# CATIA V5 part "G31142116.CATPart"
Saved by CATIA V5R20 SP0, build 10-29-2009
Part number: G31209022
Revision: 11
Definition: design
Nomenclature: G31209022
Source: made
Description: NOT SPECIFIED
Bounding box of the stored display mesh (mm): x -5 to 22, y -8 to 8, z -8 to 8
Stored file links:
  C:\Users\Raffaele\Desktop\3D X SITO CF\BOLEX\23-BUSH REF 312\G31142116.CATPart

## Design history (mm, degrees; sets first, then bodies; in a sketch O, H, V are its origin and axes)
Body1 "MANIFOLD_SOLID_BREP #5459" (main body)
  Solid1: solid without history
Body2 "MANIFOLD_SOLID_BREP #5602"
  Solid2: solid without history
Body3 "MANIFOLD_SOLID_BREP #5745"
  Solid3: solid without history
Body4 "MANIFOLD_SOLID_BREP #5888"
  Solid4: solid without history
Body5 "MANIFOLD_SOLID_BREP #6031"
  Solid5: solid without history
Body6 "MANIFOLD_SOLID_BREP #6174"
  Solid6: solid without history
Body7 "MANIFOLD_SOLID_BREP #6317"
  Solid7: solid without history
Body8 "MANIFOLD_SOLID_BREP #6462"
  Solid8: solid without history
Body9 "MANIFOLD_SOLID_BREP #6607"
  Solid9: solid without history
Body10 "MANIFOLD_SOLID_BREP #6752"
  Solid10: solid without history
Body11 "MANIFOLD_SOLID_BREP #6897"
  Solid11: solid without history
Body12 "MANIFOLD_SOLID_BREP #7040"
  Solid12: solid without history
Body13 "MANIFOLD_SOLID_BREP #7183"
  Solid13: solid without history
Body14 "MANIFOLD_SOLID_BREP #7328"
  Solid14: solid without history
Body15 "MANIFOLD_SOLID_BREP #7473"
  Solid15: solid without history
Body16 "MANIFOLD_SOLID_BREP #7618"
  Solid16: solid without history
Body17 "MANIFOLD_SOLID_BREP #7763"
  Solid17: solid without history
Body18 "MANIFOLD_SOLID_BREP #7908"
  Solid18: solid without history
Body19 "MANIFOLD_SOLID_BREP #8053"
  Solid19: solid without history
Body20 "MANIFOLD_SOLID_BREP #8196"
  Solid20: solid without history
Body21 "MANIFOLD_SOLID_BREP #8339"
  Solid21: solid without history
Body22 "MANIFOLD_SOLID_BREP #8484"
  Solid22: solid without history
Body23 "MANIFOLD_SOLID_BREP #8629"
  Solid23: solid without history
Body24 "MANIFOLD_SOLID_BREP #8774"
  Solid24: solid without history
Body25 "MANIFOLD_SOLID_BREP #8919"
  Solid25: solid without history
Body26 "MANIFOLD_SOLID_BREP #9064"
  Solid26: solid without history
Body27 "MANIFOLD_SOLID_BREP #9207"
  Solid27: solid without history
Body28 "MANIFOLD_SOLID_BREP #9352"
  Solid28: solid without history
Body29 "MANIFOLD_SOLID_BREP #9497"
  Solid29: solid without history
Body30 "MANIFOLD_SOLID_BREP #9640"
  Solid30: solid without history
Body31 "MANIFOLD_SOLID_BREP #9785"
  Solid31: solid without history
Body32 "MANIFOLD_SOLID_BREP #9930"
  Solid32: solid without history
Body33 "MANIFOLD_SOLID_BREP #10073"
  Solid33: solid without history
Body34 "MANIFOLD_SOLID_BREP #10216"
  Solid34: solid without history
Body35 "MANIFOLD_SOLID_BREP #10359"
  Solid35: solid without history
Body36 "MANIFOLD_SOLID_BREP #10502"
  Solid36: solid without history
Body37 "MANIFOLD_SOLID_BREP #10647"
  Solid37: solid without history
Body38 "MANIFOLD_SOLID_BREP #10792"
  Solid38: solid without history
Body39 "MANIFOLD_SOLID_BREP #10937"
  Solid39: solid without history
Body40 "MANIFOLD_SOLID_BREP #11082"
  Solid40: solid without history
Body41 "MANIFOLD_SOLID_BREP #11227"
  Solid41: solid without history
